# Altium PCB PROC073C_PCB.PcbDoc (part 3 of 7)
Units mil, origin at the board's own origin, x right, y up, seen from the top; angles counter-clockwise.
Board outline 2165.35 x 2695.12 mil, 8 copper layers (Top Layer, L2_GND, L3_SIGNAL 1, L4_SIGNAL 2, L5_SIGNAL 3, L6_SIGNAL 4, L7_GND, Bottom Layer), stack 55.9 mil thick; 393 components, 319 nets, 1311 pads, 1643 vias.
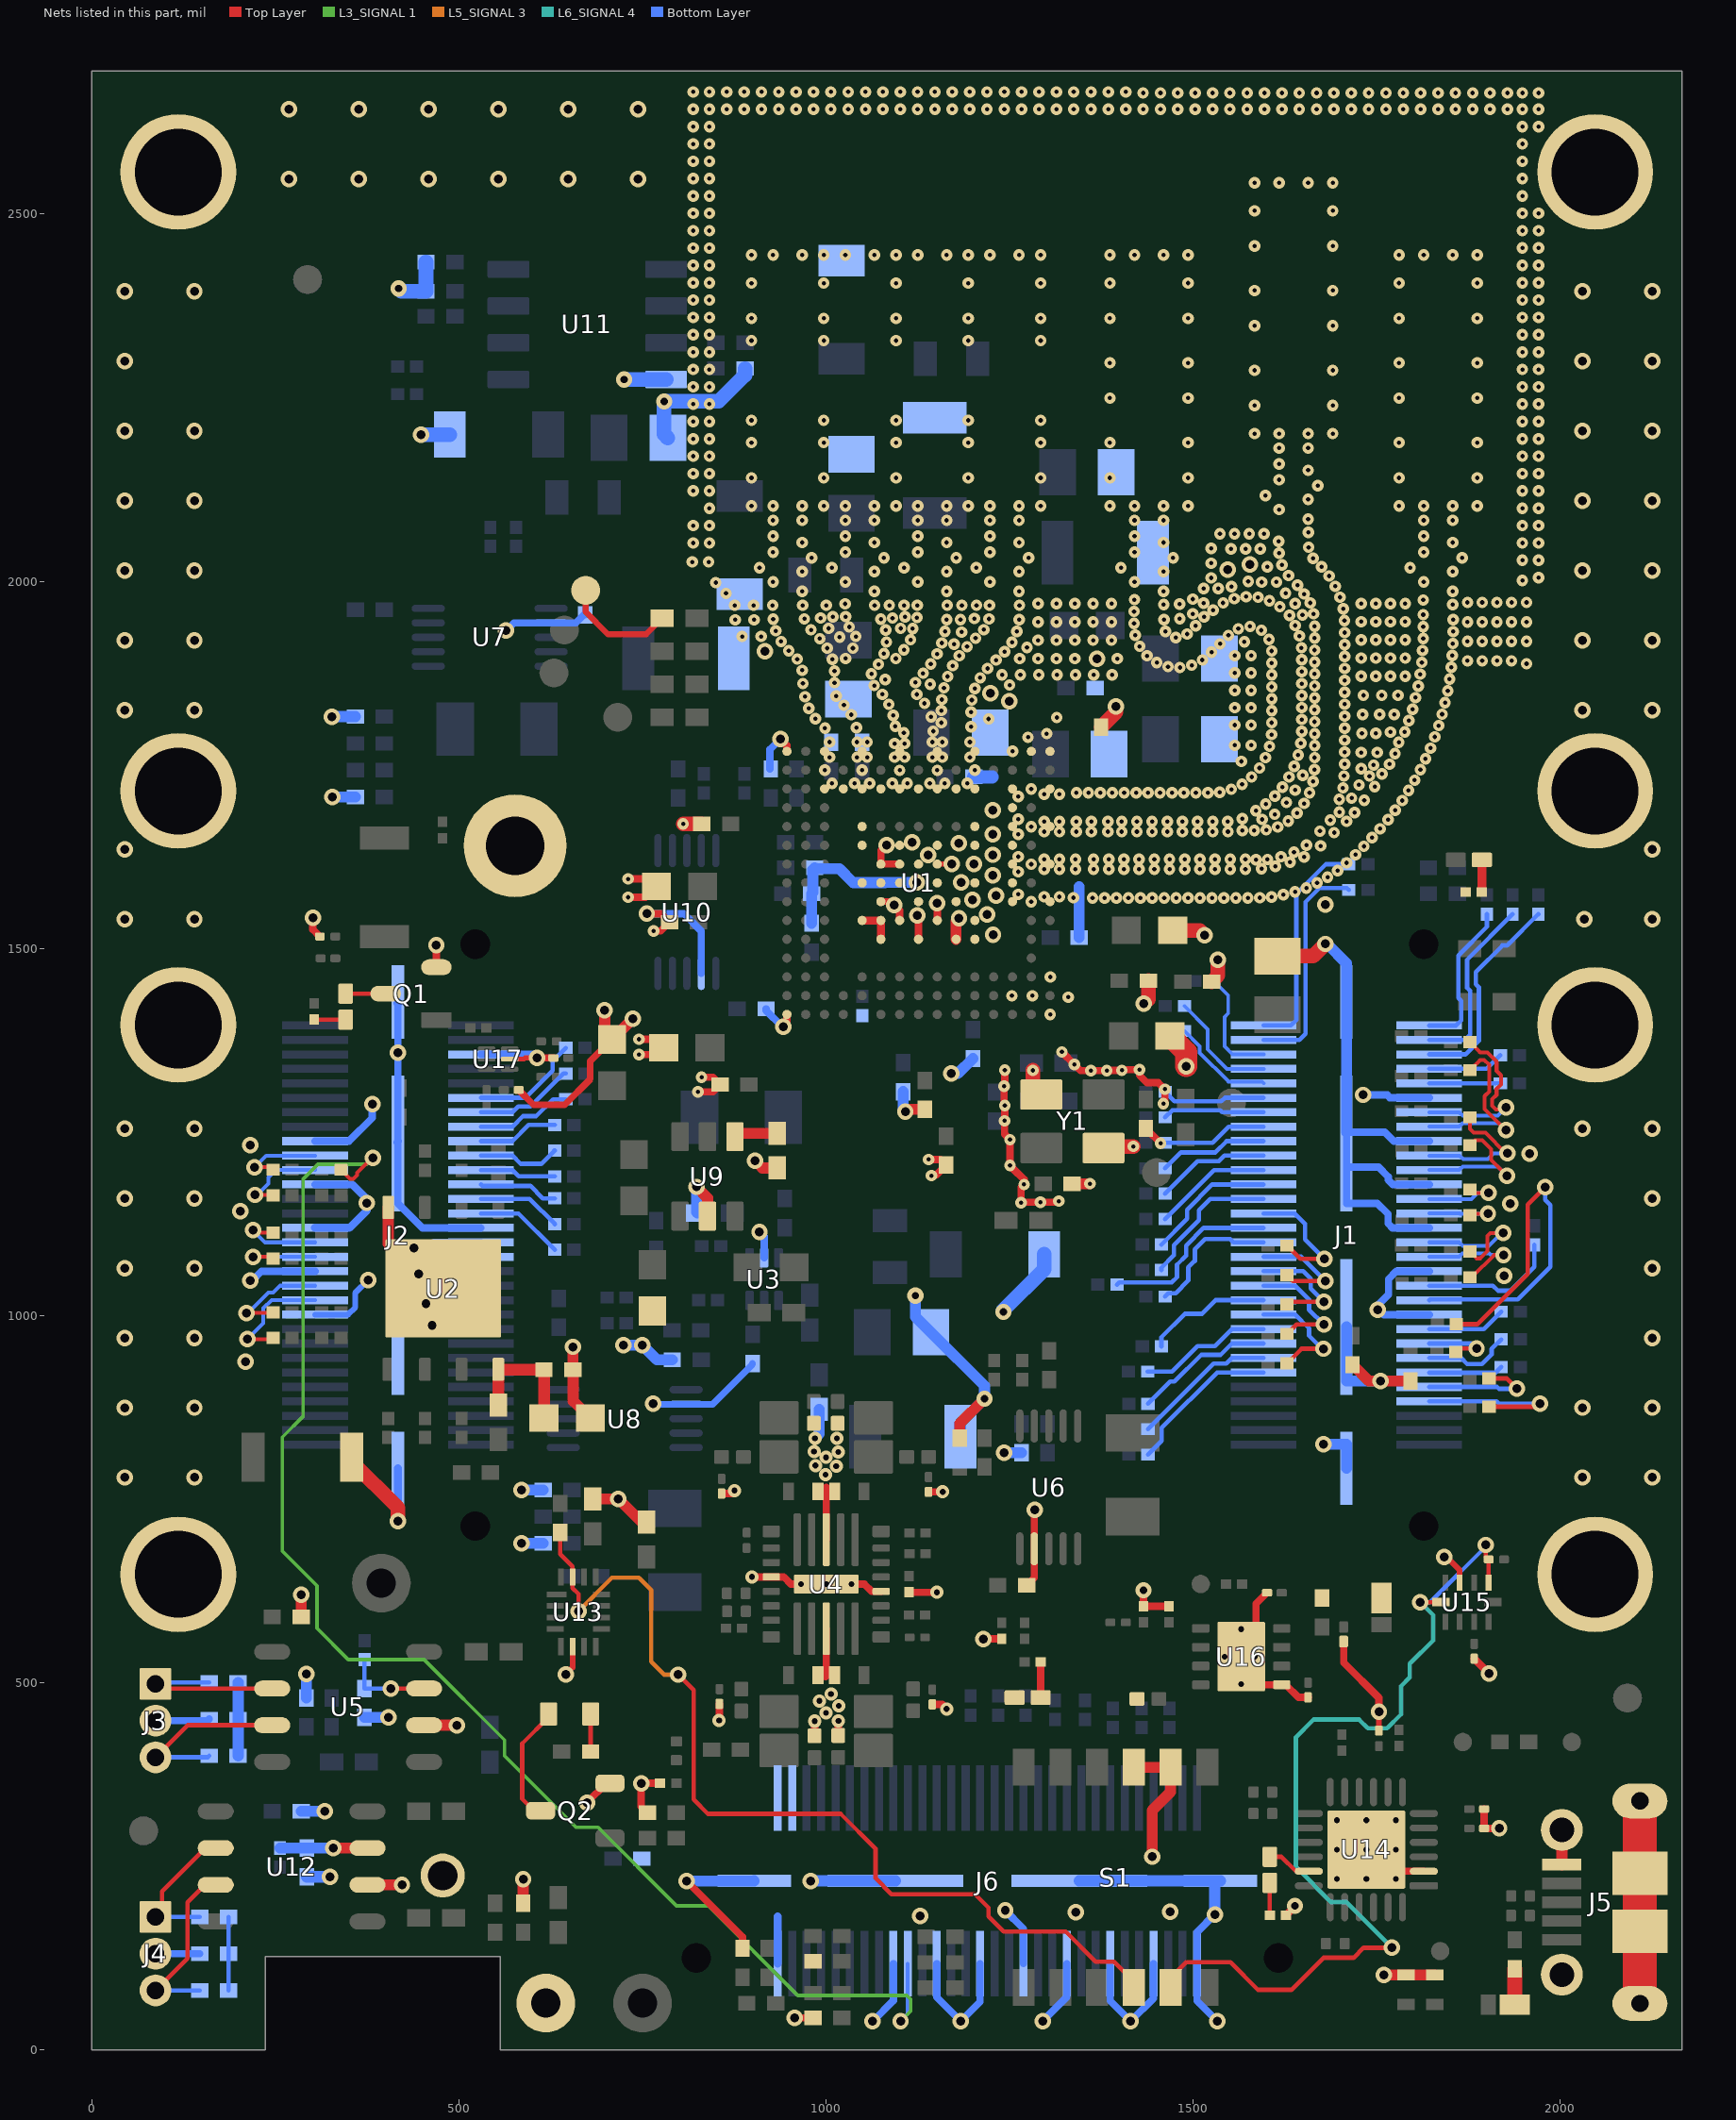
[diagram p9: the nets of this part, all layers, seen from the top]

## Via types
v1: diameter 13.77/15.74 (per signal layer), hole 5.9, Top Layer to L2_GND, tented both sides, 894 vias
v2: diameter 22.4, hole 12.2, Top Layer to Bottom Layer, tented both sides, 510 vias
v3: diameter 18, hole 8, Top Layer to Bottom Layer, tented both sides, 74 vias
v4: diameter 13.78/15.75 (per signal layer), hole 5.9, Top Layer to L2_GND, tented both sides, 72 vias
v5: diameter 22, hole 10, Top Layer to Bottom Layer, tented both sides, 61 vias
v6: diameter 19.68, hole 7.87, Top Layer to Bottom Layer, 16 vias
v7: diameter 13.77/15.74 (per signal layer), hole 5.9, Top Layer to L2_GND, tented top, 14 vias
v8: diameter 20, hole 10, Top Layer to Bottom Layer, tented both sides, 1 vias
v9: diameter 13.78/15.75 (per signal layer), hole 5.9, Top Layer to L2_GND, tented top, 1 vias

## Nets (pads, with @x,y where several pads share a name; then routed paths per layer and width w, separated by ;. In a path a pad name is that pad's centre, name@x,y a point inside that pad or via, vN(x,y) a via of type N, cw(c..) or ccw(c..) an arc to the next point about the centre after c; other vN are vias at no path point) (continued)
GND: C1.1 C2.1 C3.1 C4.1 C5.1 C6.1 C7.1 C8.1 C9.1 C10.1 C11.1 C12.1 C13.1 C14.1 C15.1 C16.1 C17.1 C18.1 C19.1 C20.1 C21.1 C22.1 C23.1 C24.1 C25.1 C26.1 C27.1 C28.1 C29.1 C30.2 C31.1 C32.1 C33.1 C34.1 C35.1 C36.1 C37.1 C38.1 C39.1 C40.1 C41.1 C42.1 C43.2 C44.1 C45.1 C46.1 C47.2 C48.2 C49.2 C50.2 C51.2 C52.1 C53.2 C54.2 C55.2 C56.2 C57.1 C58.1 C59.1 C60.2 C61.2 C62.2 C63.1 C64.1 C65.1 C66.2 C67.2 C68.2 C69.2 C70.2 C71.2 C72.2 C73.2 C74.2 C75.2 C76.2 C77.2 C78.2 C79.2 C80.2 C81.2 C82.2 C83.2 D6.2 J1.20 J1.26 J1.32 J1.38 J1.44 J1.50 J1.MP1 J1.MP2 J1.MP3 J1.MP4 J2.19 J2.25 J2.28 J2.30 J2.31 J2.32 J2.37 J2.43 J2.56 J2.MP1 J2.MP2 J2.MP3 J2.MP4 J3.2 J4.2 J5.5 J5.6 J5.7 J5.8 J5.9 J5.10 J5.11 J6.18 J6.24 J6.30 J6.36 J6.42 J6.48 J6.54 J6.60 J6.MP1 J6.MP2 J6.MP3 J6.MP4 pad.TH1 pad.TH2 pad.TH3 pad.TH4 pad.TH5 pad.TH6 pad.TH7 pad.TH8 pad.TH9 Q1.2 Q2.2 R57.2 R71.2 R84.2 R89.1 R95.1 R99.1 R101.1 R103.1 R113.1 R114.1 R116.1 R117.1 R119.2 R120.1 R121.1 R146.1 R147.1 R152.1 R155.1 R158.1 R162.1 R182.1 R194.1 R197.1 R201.1 R205.1 R208.1 R211.1 R212.2 R215.1 S1.8 S1.9 S2.2 TP11.1 TP12.1 U1.A1 U1.A3 U1.A5 U1.A7 U1.A9 U1.A13 U1.A15 U1.B1 U1.B3 U1.B5 U1.B7 U1.B9 U1.B14 U1.C1 U1.C3 U1.C4 U1.C5 U1.C6 U1.C7 U1.C8 U1.C9 U1.C14 U1.E1 U1.E2 U1.E3 U1.E5 U1.E6 U1.E8 U1.E10 U1.E11 U1.F3 U1.F9 U1.F11 U1.G1 U1.G2 U1.G3 U1.G6 U1.G7 U1.G8 U1.G10 U1.H3 U1.H7 U1.H9 U1.H11 U1.J1 U1.J2 U1.J3 U1.J6 U1.J7 U1.J8 U1.J10 U1.K3 U1.K7 U1.K8 U1.K9 U1.K10 U1.K11 U1.L1 U1.L2 U1.L3 U1.L5 U1.L6 U1.L8 U1.L10 U1.M3 U1.N1 U1.N2 U1.N3 U1.R1 U1.R15 U2.4 U2.9 U3.2 U4.4 U4.11 U4.17 U4.24 U4.27 U5.2 U6.7 U7.7 U8.7 U9.2 U10.7 U11.4 U12.2 U13.6 U14.2 U14.25 U15.3 U16.5 U16.9@1565.44,535.87 U17.2 Y1.2 Y1.4 | length 10819.2
  Top Layer w6.6: U17.2@569.32,1349.48 588.76,1349.48 590.34,1351.06 v2(606.52,1351.06)
  Top Layer w7: U1.J7@1100.38,1613.73 U1.J7@1100.39,1614.98 U1.J7@1100.38,1615.45 ; U1.G7@1151.57,1614.98 U1.G7@1151.57,1614.98 v2(1171.17,1614.99)
  Top Layer w7.87: v2(645.83,511.84) 654.91,520.93 U13.6@654.91,549.7 ; R95.1@1752.9,434.99 v2(1752.9,460.83) ; v2(1842.08,671.49) 1842.08,673.64 1842.33,673.89 1862.92,653.3 U15.3@1862.92,636.55
  Top Layer w9: C53.2@581.57,1307.45 601.6,1287.42 644.39,1287.42 679.2,1322.23 679.2,1346.72 C70.2@708.74,1376.27 ; U1.K9@1074.8,1563.8 1088.56,1563.8 v2(1093.07,1559.29)
  Top Layer w9.42: U14.25@1765.34,243.51 U14.2@1814.14,243.51
  Top Layer w9.8: C57.1@1273.23,632.76 1283.67,643.2 U6.7@1283.67,682.61 1283.67,735.46 v2@1284.13,735.91 ; U16.9@1565.44,535.87 1585.43,555.87 1585.43,607.67 C50.2@1600.53,622.77
  Top Layer w9.84: v2(301.25,1542) 301.25,1526 R215.1@310.87,1516.38 ; v2(606.52,1351.06) C52.1@629.01,1351.06
  Top Layer w10: Q1.2@469.47,1474.62 v2(469.47,1504.44) ; v2(674.94,336.95) 674.94,337.43 Q2.2@700.91,363.4 ; v1(730.59,1569.77) 754.09,1569.77 C17.1@769.1,1584.77 769.09,1585.32 759.39,1595.02 759.14,1594.77 v1(730.59,1594.77) ; v1(745.29,1355.67) 769.99,1355.67 C27.1@779.1,1364.77 767.39,1376.47 v1(745.29,1376.47) ; v2(756,1547.48) 775.19,1547.48 C21.1@786.91,1535.77 775,1523.86 v1(765.4,1523.86) ; R182.1@756.92,323.18 748.32,331.78 v2(748.32,363.4) R201.1@774.18,363.4 ; v2(810.16,230.33) 886.26,154.23 R208.1@886.26,138.67 ; v1(825.59,1304.77) 845.9,1304.77 C25.1@855.91,1314.77 845.9,1324.77 v1(830.59,1324.77) ; v3@854.8,449.13 C54.2@854.8,471.53 C54.2@854.8,471.76 ; C56.2@857.9,757.89 871.42,757.89 v3(875.53,762) ; v3(899.33,644.48) 899.49,644.32 U4.4@925.53,644.32 942.38,644.32 952.22,634.48 v6(966.08,634.48) v6(1000.33,634.48) ; v2(937.97,1785.39) 946.84,1776.52 U1.R1@946.84,1768.52 ; v2(941.65,1393.42) 946.84,1398.61 U1.R15@946.84,1410.25 ; v2(957.39,43.89) R205.1@982.36,43.89 ; C61.2@984.22,427.67 C61.2@984.51,427.96 984.51,447.67 v3(984.8,447.97) ; 999.44,508.58 1000.33,509.47 U4.11@1000.33,573.85 ; 1000.26,766.4 1000.33,766.33 U4.24@1000.33,695.11 ; v6(1000.33,634.48) 1052.53,634.44 1062.34,624.64 U4.17@1075.13,624.64 ; C62.2@1016.44,428.15 C62.2@1016.73,428.44 1016.73,448.15 v3(1017.02,448.44) ; v2(1082.37,1640.84) 1074.79,1633.26 U1.K7@1074.8,1614.98 U1.J7@1100.39,1614.98 ; v2(1093.07,1559.29) 1100.38,1551.98 U1.J10@1100.39,1538.2 ; C68.2@1112.94,623.46 v3(1150.97,623.46) ; v2(1124.47,1544.89) 1125.97,1543.39 U1.H11@1125.98,1512.61 ; C60.2@1139.71,760.24 v3(1158.91,760.24) ; v1(1139.92,1212.73) 1155.94,1212.73 C16.1@1163.59,1205.09 1150.59,1192.08 1145.09,1192.08 v1(1143.74,1190.73) ; C55.2@1144.8,470.87 1158.49,470.87 1164.3,465.06 v3(1164.3,464.54) ; U1.G10@1151.57,1538.2 v2(1151.57,1561.79) ; v2(1214.24,559.92) R194.1@1239.41,559.92 ; v1(1243.49,1334.27) 1243.59,1334.17 1243.59,1313.42 v1(1242.66,1312.49) 1242.66,1286.9 v1(1243.49,1286.07) 1243.49,1265.87 v1(1243.09,1265.47) 1243.09,1247.27 v1(1250.59,1239.77) v1(1250.59,1204.77) 1269.74,1185.62 v1(1269.74,1178.77) 1265.69,1174.72 v1(1265.69,1153.99) ; v1@1250.2,1204.38 1260.59,1193.99 ; v1@1266.29,1154.59 v1(1291.99,1154.59) v1@1315.69,1154.59 ; v1(1321.28,1359.2) v1(1338.23,1342.25) 1346.73,1333.75 v1(1360.63,1333.75) v1(1382.33,1333.75) 1382.73,1334.15 v1(1402.93,1334.15) 1403.93,1335.15 v1(1427.03,1335.15) 1427.03,1327.48 1437.24,1317.26 1452.71,1317.26 v1(1461.53,1308.45) 1461.53,1290.77 v1(1459.43,1288.67) ; Y1.2@1377.91,1228.35 Y1.2@1380.15,1230.59 ; v5(1432.29,626.22) 1432.29,604.6 R120.1@1432.23,604.53 R119.2@1467.08,604.53 ; C32.1@1435.59,1255.09 1435.59,1254.77 v1(1455.59,1234.77) ; U16.9@1565.44,535.87 1565.44,525.48 1593.43,497.49 U16.5@1620.56,497.49 1626.21,497.49 1643.3,480.39 C49.2@1656.37,480.39 ; R99.1@1626.3,183.64 1638.37,195.71 v5(1638.37,196.39) ; C51.2@1704.92,556.41 1704.92,527.79 1752.9,479.81 v2(1752.9,460.83) ; C45.1@1896.13,328.23 C44.1@1896.13,301.92 v2(1916.7,301.92)
  Top Layer w10.34: C48.2@1882.6,533.1 v2(1902.71,512.98)
  Top Layer w11: U1.L10@1049.21,1538.2 U1.K10@1074.8,1538.2 U1.K11@1074.8,1512.61
  Top Layer w15: C38.1@285.31,589.74 v2(285.31,620.19) ; U12.2@375.78,225.13 v2(422.64,225.13) ; U2.4@403.88,1147.43 403.88,1098.19 U2.9@464.88,1037.19 ; U5.2@452.64,442.41 v2(497.63,442.41) ; R84.2@587.71,199.85 v2(587.71,232.68) ; v2(655.38,957.66) C34.1@655.38,926.67 655.76,926.29 655.76,883.87 C35.1@679,860.63 ; C43.2@682.22,750.38 v2(717.37,750.38) 748.9,718.85 R89.1@755.42,718.85 ; v2(698.74,1415.77) 698.74,1386.27 C70.2@708.74,1376.27 v2(736.99,1404.52) ; v2(823.74,1175.44) 838.74,1160.44 U9.2@838.74,1135.64 ; v2(903.51,1211.03) 913.39,1201.15 C71.2@933.74,1201.15 ; v2(1108,1277.77) 1111.31,1281.08 C26.1@1135.59,1281.08 ; U1.F11@1177.16,1512.61 1177.15,1537.17 v2(1181.17,1541.19) ; R101.1@1182.13,833.56 1182.13,853.17 v5(1215.98,887.02) ; C33.1@1335.28,1179.77 v7(1359.59,1179.77) ; S1.9@1419.21,385.15 S1.8@1469.21,385.15 1469.21,351.48 1444.06,326.33 v2(1444.06,263.31) ; R155.1@1717,933.25 1739.05,911.21 v2(1754.94,911.21) R152.1@1795.94,911.21 ; v2(1759.55,102.28) C46.1@1789.78,102.28 C47.2@1828.84,102.28
  Top Layer w15.75: J5.5@2001.97,252.56 J5.10@2001.97,299.81
  Top Layer w20: S2.2@354.03,807.23 354.03,801.78 417.24,738.58 v2(417.24,720.07) ; v1(805.59,1669.77) C28.1@830.91,1669.77 ; v1(1281.8,1334.05) 1281.8,1312.65 Y1.4@1293.27,1301.19 ; C4.1@1374.59,1801.45 1395,1821.86 v2(1395,1829.77) ; Y1.2@1380.15,1230.59 v1(1418.59,1230.59) ; v2(1432.59,1424.77) 1438.87,1431.04 C5.1@1438.87,1456.18 ; C22.1@1472.09,1524.77 1508.78,1524.77 v2(1515.66,1517.89) ; C14.1@1525.28,1454.77 1533.74,1463.23 v2(1533.74,1484.77) ; C15.1@1615,1489.77 1663.54,1489.77 v2(1680,1506.23)
  Top Layer w30: C18.1@1468.28,1381.18 1490.59,1358.86 v2(1490.59,1339.77)
  Top Layer w46: J5.6@2108.27,63.58 J5.7@2108.27,162.01 J5.8@2108.27,240.75 J5.9@2108.27,339.18
  Bottom Layer w8: J2.19@304.44,1001.5 349.08,1001.5 359.13,1011.55 359.13,1030.82 358.98,1030.98 v2(376.73,1048.73)
  Bottom Layer w9: v2@763.74,874.45 768.87,879.59 U8.7@809.52,879.59 846,879.59 900,933.58 C36.1@900,935.09
  Bottom Layer w9.84: J2.56@530.04,1355.83 601.75,1355.83 v2(606.52,1351.06) ; v2(564.49,1932.97) 574.94,1943.43 U7.7@625.74,1943.43 659.49,1943.43 670.12,1954.06 C58.1@672.08,1954.06
  Bottom Layer w10: J4.2@87.13,131.4 C42.1@147.3,131.4 ; J3.2@87.13,448.74 158.26,448.74 C39.1@160.26,450.74 ; v2(216.24,1048.08) 218.91,1048.08 231.39,1060.56 J2.25@304.44,1060.56 ; J2.37@304.44,1178.67 355.06,1178.67 375,1158.73 v2(375,1153.56) ; J2.43@304.44,1237.72 350.49,1237.72 382.3,1269.53 v2(382.3,1288.09) ; J2.MP4@417.24,1427.29 415.92,1425.97 417.41,1424.48 417.02,1424.09 v2(417.02,1358.35) 417.02,1237.97 417.41,1237.58 415.92,1236.09 J2.MP3@417.24,1234.77 417.24,1152.87 450.49,1119.61 J2.32@530.04,1119.61 ; v2(438.88,1092.19) 458.18,1092.19 465.92,1099.93 J2.30@530.04,1099.93 ; v2(445.36,1056.61) 468.99,1080.24 J2.28@530.04,1080.24 ; v2(756,1547.48) 806.28,1547.48 830.27,1523.49 U10.7@830.28,1466.11 ; v2(909.46,1114.3) 915.74,1108.02 U3.2@915.74,1078.9 ; C63.1@918.43,1417.96 918.42,1415.49 940.5,1393.42 v2(941.65,1393.42) ; R146.1@923.74,1744.45 923.74,1771.16 v2(937.97,1785.39) ; v2(1063.3,39.43) 1063.85,39.43 1091.79,67.37 J6.18@1091.79,117.69 ; J6.24@1150.84,117.69 1150.84,72.17 v2(1183.58,39.43) 1209.9,65.74 J6.30@1209.9,117.69 ; v2(1244.15,190.65) v2@1243.52,190.65 ; J6.36@1268.95,117.69 1268.95,165.22 v2@1243.52,190.65 ; v2(1294.98,39.43) 1328.01,72.46 J6.42@1328.01,117.69 ; J6.48@1387.06,117.69 1387.06,67.26 v2(1414.9,39.43) 1445.89,70.42 1445.89,117.46 J6.54@1446.12,117.69 ; v2(1529.43,184.88) 1505.17,160.61 J6.60@1505.17,117.69 1505.17,67.26 v2(1533.01,39.43) ; v2(1731.57,1300.7) 1731.76,1300.52 1764.48,1300.52 1767.77,1297.23 ; 1767.77,1296.78 J1.50@1821.54,1296.78 ; 1775.49,1119.61 J1.32@1821.54,1119.61 1771.25,1119.61 1765.35,1125.52 1765.35,1138.41 1750.74,1153.01 1708.74,1153.01 J1.MP3@1708.74,1202.38 ; J1.20@1821.54,1001.5 1759.57,1001.5 1753.07,1008 v2(1751.37,1008) 1751.37,1014.28 1765.97,1028.88 1765.97,1049.94 1776.59,1060.56 J1.26@1821.54,1060.56 ; J1.38@1821.54,1178.67 1771.93,1178.67 1765.62,1184.98 1765.62,1189.3 1752.54,1202.38 J1.MP3@1708.74,1202.38 ; J1.44@1821.54,1237.72 1773.14,1237.72 1760.84,1250.02 1708.74,1250.02 J1.MP3@1708.74,1234.77 J1.MP3@1708.74,1202.38 ; v2@1243.52,190.65 1243.16,191.01 1243.03,190.88 1243.25,190.65 v2@1243.52,190.65
  Bottom Layer w11: J2.31@304.44,1119.61 351.2,1119.61 375,1143.42 v2(375,1153.56) ; v2(417.24,720.07) J2.MP1@417.24,792.25
  Bottom Layer w15: C41.1@285.33,325.13 v2(317.37,325.13) ; R71.2@292.59,479.59 v2(292.59,512.16) ; v2(326.97,1815.73) R113.1@359.16,1815.75 ; v2(327.89,1706.46) R114.1@359.16,1706.46 ; C37.1@371.69,453.04 v2(404.26,453.04) ; J2.MP2@417.24,984.77 419.2,986.73 v2(463.71,986.73) ; v2(585.46,690.14) R117.1@614.95,690.14 ; v2(585.46,762.57) R116.1@614.95,762.57 ; v2(723.95,959.77) v2(750,959.77) 769.68,940.08 C59.1@790.63,940.08 ; v2(810.16,230.33) 902.07,230.33 J6.MP1@902.22,230.48 ; v2(823.74,1175.44) 823.74,1141.15 R197.1@825.12,1139.77 ; v2(979.45,230.48) J6.MP2@1094.74,230.48 ; C10.1@980.28,1574.77 980.27,1534.77 C29.1@980.59,1534.45 ; C10.1@980.28,1574.77 982.13,1576.62 982.13,1607.21 R147.1@984.69,1609.77 985.87,1608.59 1018.39,1608.59 1037.21,1589.77 1079.88,1589.77 1080,1589.89 v2(1123.47,1589.89) ; v3(985.07,833.21) 990.93,839.07 R57.2@990.93,872.48 ; C30.2@1105,1305.08 1105,1280.77 v2(1108,1277.77) ; v5(1121.81,1027.3) 1121.81,998.47 C83.2@1142.52,977.76 ; C83.2@1142.93,977.35 1215.98,904.3 v5(1215.98,887.02) 1183.23,854.27 C82.2@1183.23,835.48 ; v2(1170.59,1329.77) 1179.68,1329.77 C9.1@1200,1350.09 ; v2(1242.56,813.46) R103.1@1266.47,813.46 ; C6.1@1344.69,1514.77 1344.68,1584.45 ; J6.MP3@1344.74,230.48 J6.MP4@1531.53,230.48 ; v2(1529.43,184.88) 1529.43,228.38 J6.MP4@1531.53,230.48 ; J6.MP4@1537.26,230.48 J6.MP4@1531.53,230.48 ; v2(1677.33,824.84) 1708.74,824.84 J1.MP1@1708.74,792.25 ; v2(1680,1506.23) 1682.3,1506.23 1708.74,1479.79 J1.MP4@1708.74,1427.29 J1.MP3@1708.74,1250.02 ; J1.MP2@1708.74,984.77 1708.74,911.21 v2(1754.94,911.21)
  Bottom Layer w16: C40.1@293.22,235.76 v2(324.43,235.76)
  Bottom Layer w18: C12.1@1201.28,1733.77 1226,1733.77
  Bottom Layer w20: v5(418,2398.77) 422,2394.77 R158.1@455.32,2394.77 C65.1@455.32,2434.77 ; v2(448.61,2199.7) C64.1@487.92,2199.7 ; v5(725,2274.77) U11.4@782.28,2274.77 ; C81.2@784.63,2195.15 779.59,2200.19 v5(779.59,2245.04) 853.81,2245.04 889.68,2280.92 R162.1@889.69,2289.77 ; v5(1241.47,1005.29) 1241.47,1007.6 1297.08,1063.21 C1.1@1297.08,1083.72
  other v1: 1317.09,1155.99 1305.31,1410.05 1330,1433.77 1253.08,1435.63 1281.08,1435.63 1305.58,1461.22 1279.52,1563.79 1337.05,1569.18 1362.97,1568.78 1379.24,1568.78 1395.5,1568.78 1411.77,1568.78 1428.03,1568.78 1444.3,1568.78 1460.56,1568.78 1476.83,1568.78 1493.09,1568.78 1509.36,1568.78 1525.62,1568.78 1541.89,1568.78 1558.15,1568.78 1574.42,1568.78 1590.68,1569.15 1606.91,1570.21 1297.24,1570.4 1317.9,1570.4 1622.9,1573.19 1261.81,1573.82 1638.67,1577.17 1654.07,1582.39 1668.78,1589.34 1683.02,1597.19 1261.81,1604.53 1696.54,1606.23 1297.24,1607.95 1317.9,1607.95 1279.52,1614.77 1709,1616.68 1297.23,1621.58 1317.89,1621.58 1261.8,1625 1720.95,1627.71 1732.45,1639.22 1673.43,1639.68 1743.69,1650.98 1261.8,1655.71 1297.23,1659.13 1317.89,1659.13 1566.95,1660.76 1583.22,1660.76 1599.46,1661.55 1754.61,1663.03 1279.51,1665.95 1615.23,1665.56 1297.23,1672.76 1317.89,1672.76 1547,1672.77 1708.91,1673.15 1629.44,1673.45 1261.8,1676.18 1765.24,1675.34 1567,1676.77 1641.4,1684.48 1719.83,1685.2 1585.34,1687.75 1774.93,1688.4 1598.86,1696.79 1651.14,1697.51 1784.62,1701.47 1698.87,1703.23 1715.74,1704.77 1261.8,1706.89 1611.09,1707.52 1297.23,1710.31 1317.89,1710.31 1341,1711.94 1357.27,1711.94 1373.53,1711.94 1389.8,1711.94 1406.06,1711.94 1422.33,1711.94 1438.59,1711.94 1454.86,1711.94 1471.12,1711.94 1487.39,1711.94 1503.65,1711.94 1519.92,1711.94 1658.5,1712.01 1536.15,1712.84 1793.23,1715.27 1279.51,1717.13 1551.94,1716.75 1621.65,1719.88 1725.74,1722.77 1566.61,1723.78 1008.26,1725.01 1038.97,1725.01 1059.44,1725.01 1090.15,1725.01 1110.62,1725.01 1141.33,1725.01 1161.8,1725.01 1192.51,1725.01 1663.26,1727.56 1801.59,1729.22 1579.54,1733.64 1630.47,1733.55 1705.38,1735.05 1740,1734.77 1049.21,1742.93 1100.39,1742.72 1151.57,1742.72 1202.75,1742.93 1665.28,1743.7 1809.41,1743.48 1728.74,1744.93 1590.31,1745.83 1637.61,1748.16 1745.74,1749.77 1767.26,1751.02 1706.22,1751.29 1565.74,1754.77 1816.36,1758.18 1598.46,1759.9 1665.42,1759.97 1004.84,1760.44 1042.39,1760.44 1056.02,1760.44 1093.57,1760.44 1107.2,1760.44 1144.75,1760.44 1158.38,1760.44 1195.93,1760.44 1642.96,1763.53 1774.81,1765.42 1728.74,1766.93 1750.74,1766.93 1706.22,1767.56 1254.13,1768.73 1823.27,1772.91 1603.95,1775.22 1665.42,1776.23 1556.74,1776.72 1578.9,1776.72 1093.57,1779.1 1107.2,1779.1 1646.44,1779.41 1004.84,1781.1 1042.39,1781.1 1056.02,1781.1 1144.75,1781.1 1158.38,1781.1 1195.93,1781.1 1706.22,1783.82 1275.08,1787.63 1828.85,1788.19 1606.59,1791.26 1300.58,1792.63 1665.42,1792.49 1729.74,1792.88 1748.74,1792.88 1106,1793.77 1768.74,1794.77 1788.14,1795.09 1146.02,1795.85 1647.72,1795.63 998.62,1799.93 1706.22,1800.09 1041.46,1800.71 1197.56,1801.87 1094.35,1802.77 1834.33,1803.5 1556.74,1804.28 1578.9,1804.28 1157.08,1807.49 1607,1807.52 1665.42,1808.76 1793.62,1810.41 1647.79,1811.89 985.62,1812.93 1221.58,1812.63 1314.28,1814.53 1143.22,1815.56 1706.22,1816.35 1091.55,1817.33 1034.33,1818.45 1730.74,1818.82 1753.74,1818.82 1773.74,1818.82 1838.99,1819.08 1197.56,1822.07 1157.08,1824.03 1607,1823.79 1665.42,1825.02 1798.77,1825.83 976.62,1826.93 1556.74,1827.9 1578.9,1827.9 1647.79,1828.16 1024.45,1831.37 1085.58,1832.46 1706.22,1832.62 1134.21,1833.76 1842.94,1834.86 1157.74,1838.9 1198.59,1838.3 1607,1840.05 1665.42,1841.29 1802.72,1841.61 971.62,1842.93 1013.89,1843.74 1647.79,1844.42 1731.74,1844.77 1756.74,1844.77 1778.74,1844.77 1076.69,1846.08 1123.56,1846.05 1706.22,1848.88 1846.71,1850.68 1556.74,1851.52 1578.9,1851.52 1202.74,1854.03 1160.66,1854.9 1607,1856.32 1065.72,1858.09 1665.42,1857.55 1806.61,1857.4 1250,1858.77 1141.94,1859.75 968.62,1860.93 1647.79,1860.69 1011.62,1861.93 1121.92,1862.23 1706.22,1865.14 1080.65,1866.12 1849.1,1866.77 1209.99,1868.59 1165.67,1870.38 1728.74,1870.71 1748.74,1870.71 1768.74,1870.71 1788.74,1870.71 1239.74,1872.77 1264.74,1872.77 1289.74,1872.77 1314.74,1872.77 1339.74,1872.77 1364.74,1872.77 1389.74,1872.77 1607,1872.58 1061.86,1873.89 1665.42,1873.82 1809,1873.49 1132.26,1874.79 1556.74,1875.15 1578.9,1875.15 1647.79,1876.95 1011.62,1877.93 967.62,1878.93 1220.05,1881.37 1706.22,1881.41 1481.97,1882.64 1851.49,1882.86 1465.75,1883.83 1172.66,1885.06 1497.93,1885.74 1071.51,1886.98 1142.67,1887.29 1953.98,1887.82 1607,1888.85 1450.42,1889.28 1665.42,1890.08 1811.38,1889.58 1873.55,1891.76 1893.53,1891.76 1913.54,1891.76 1933.52,1891.76 1231.62,1892.8 1512.54,1892.9 1647.79,1893.21 960.84,1894.05 1008.62,1893.93 1026.62,1894.93 1095.15,1894.89 1263.74,1894.77 1288.74,1894.77 1313.74,1894.77 1338.74,1894.77 1396.74,1894.77 1728.74,1895.48 1748.74,1895.48 1768.74,1895.48 1788.74,1895.48 1706.22,1897.67 1181.53,1898.69 1437.1,1898.61 1556.74,1898.77 1578.9,1898.77 1852.78,1899.07 1151.18,1901.15 1078.92,1901.46 1243.21,1904.21 1524.97,1903.39 1607,1905.11 949.34,1905.55 1812.41,1905.81 1106.16,1906.86 1665.42,1906.35 1001.62,1908.93 1036.62,1908.93 1273.74,1909.77 1647.44,1909.48 1192.14,1911.02 1427.08,1911.42 1706.22,1913.94 1174.3,1914.4 1536.47,1914.89 1157.62,1916.08 1853.58,1915.32 1253.2,1917.04 938.95,1918.07 1082.34,1917.36 1569.74,1917.77 1873.55,1918.26 1893.53,1918.26 1913.54,1918.26 1933.52,1918.26 1953.98,1918.26 1288.74,1919.77 1313.74,1919.77 1338.74,1919.77 1363.74,1919.77 1388.74,1919.77 1728.74,1920.24 1748.74,1920.24 1768.74,1920.24 1788.74,1920.24 1115.1,1920.45 1603.27,1920.94 991.62,1921.93 1813.21,1922.06 1203.64,1922.52 1665.42,1922.61 1018.62,1923.93 1476.3,1923.45 885.86,1924.93 911.74,1924.93 1040.62,1924.93 1644.78,1925.52 1420.97,1926.49 1547.97,1926.39 1491.83,1928.26 1706.22,1930.2 1184.62,1930.93 1162.03,1931.74 1259.92,1931.86 1462.28,1931.69 1854.01,1931.57 931.71,1932.63 979.62,1933.93 1081.18,1933.58 1215.08,1934.08 1592.84,1933.42 1003.62,1935.93 1101.66,1935.93 1561.5,1935.43 1031.62,1937.93 1577.44,1938.65 1665.42,1938.88 1813.21,1938.32 1503.49,1939.6 1419.51,1942.69 1288.74,1944.77 1313.74,1944.77 1338.74,1944.77 1363.74,1944.77 1388.74,1944.77 1728.74,1945 1748.74,1945 1768.74,1945 1788.74,1945 1873.55,1944.77 1893.53,1944.77 1913.54,1944.77 1933.52,1944.77 1953.98,1944.77 1706.05,1946.47 876.33,1947.65 902.2,1947.65 1164.35,1947.84 1263,1947.83 1460.31,1947.84 1854.01,1947.84 928.08,1948.48 970.62,1948.93 1074.71,1948.51 1222.11,1948.75 1481.65,1949.03 992.62,1949.93 1090.66,1949.93 1202.2,1949.34 1009.47,1951.64 1026.62,1951.93 1107.51,1951.64 1515,1951.77 1648.83,1954.15 1813.21,1954.59 1499.62,1955.71 1419.51,1958.96 1527,1960.77 1704.44,1962.65 1617.97,1965.39 875.62,1967.34 901.49,1967.34 927.37,1967.34 968.17,1967.34 1000.3,1967.34 1066.23,1967.34 1086.21,1967.33 1106.22,1967.34 1124.23,1967.34 1165.03,1967.34 1185,1967.33 1205.02,1967.34 1222.65,1967.34 1263.45,1967.34 1459.84,1968.26 1853.54,1968.26 1481.64,1969.04 1288.74,1969.77 1313.74,1969.77 1338.74,1969.77 1363.74,1969.77 1388.74,1969.77 1638.99,1969.78 1728.74,1969.77 1748.74,1969.77 1768.74,1969.77 1788.74,1969.77 1514.23,1970.32 1540.83,1970.69 1659.55,1970.65 1893.53,1971.26 1933.52,1971.26 1953.98,1971.26 1873.55,1971.27 1913.54,1971.27 1603.91,1973.56 1420.03,1975.02 1813.21,1974.59 1499.61,1975.72 1556.03,1976.47 1588.33,1978.22 1572.08,1979.07 1700.01,1978.3 863.94,1983.55 1625.84,1983.79 967.55,1986.23 1065.98,1986.23 1164.41,1986.23 1262.84,1986.23 1459.7,1986.25 1853.4,1986.25 1514.22,1990.33 1534.23,1990.34 1552,1992.77 1693.57,1993.24 849.84,1998.23 1593.39,1998.94 1613.4,1998.95 1575,1999.77 1948.27,2001.08 1524.57,2004.68 1970.43,2005.02 1685.24,2007.2 967.55,2013.26 1065.98,2013.26 1164.41,2013.26 1262.84,2013.26 1459.69,2013.27 1853.39,2013.27 909.5,2018.47 1007.93,2018.47 1106.36,2018.47 1204.79,2018.47 1401.65,2018.48 1795.35,2018.48 1601,2019.77 1674.91,2019.77 1620.8,2022.48 1524.56,2024.69 818.11,2026.42 840.27,2026.42 1948.27,2028.64 1970.43,2028.64 1663.37,2031.23 980.54,2031.85 1078.97,2031.85 1177.4,2031.85 1275.83,2031.85 1472.69,2031.86 1866.39,2031.86 1616.87,2038.26 928,2039.8 1026.43,2039.8 1124.86,2039.8 1223.29,2039.8 1420.15,2039.82 1813.85,2039.82 1551.47,2044.1 1571.48,2044.11 1591.46,2044.1 1524.57,2044.67 1657.16,2046.26 819.09,2052.25 841.26,2052.25 1948.27,2052.26 1970.43,2052.26 967.56,2052.8 1065.99,2052.8 1164.42,2052.8 1262.85,2052.8 1459.69,2052.82 1853.39,2052.82 1616.36,2054.52 927.99,2061.43 1026.42,2061.43 1124.85,2061.43 1223.28,2061.43 1420.14,2061.44 1813.84,2061.44 1536.37,2064.68 1556.35,2064.67 1576.36,2064.68 1596.34,2064.67 1656.69,2066.69 819.09,2075.87 841.26,2075.87 1948.27,2075.89 1970.43,2075.89 928,2083.03 967.55,2083.03 1026.43,2083.03 1065.98,2083.03 1124.86,2083.03 1164.41,2083.03 1223.29,2083.03 1262.84,2083.03 1420.15,2083.05 1459.69,2083.05 1813.85,2083.05 1853.39,2083.05 1656.55,2084.67 841.26,2099.49 1948.27,2099.51 1970.43,2099.51 898.55,2102.72 928,2102.72 967.55,2102.72 997,2102.72 1026.43,2102.72 1065.98,2102.72 1095.43,2102.72 1124.86,2102.72 1164.41,2102.72 1193.86,2102.72 1223.29,2102.72 1262.84,2102.72 1292.29,2102.72 1386.65,2102.73 1420.15,2102.73 1459.69,2102.73 1493.18,2102.73 1780.35,2102.73 1813.85,2102.73 1853.39,2102.73 1886.88,2102.73 1656.54,2111.7 1598.5,2116.9 819.09,2123.11 841.26,2123.11 1948.27,2123.13 1970.43,2123.13 1669.54,2130.29 1617,2138.25 898.55,2140.87 996.98,2140.89 1095.41,2140.89 1193.84,2140.89 1292.27,2140.89 1386.65,2140.88 1493.18,2140.88 1780.35,2140.88 1886.88,2140.88 819.09,2146.74 841.26,2146.74 1948.27,2146.75 1970.43,2146.75 1656.54,2151.24 1616.99,2159.87 819.09,2170.36 841.26,2170.36 1948.27,2170.37 1970.43,2170.37 1617,2181.47 1656.54,2181.47 898.55,2188.9 996.97,2188.9 1095.4,2188.9 1193.83,2188.9 1292.26,2188.9 1386.65,2188.91 1493.18,2188.91 1780.35,2188.91 1886.88,2188.91 819.09,2193.98 841.26,2193.98 1948.27,2194 1970.43,2194 1583.5,2201.16 1617,2201.16 1656.54,2201.16 1690.03,2201.16 819.09,2217.6 841.26,2217.6 1948.27,2217.62 1970.43,2217.62 898.55,2219.17 996.97,2219.17 1095.4,2219.17 1193.83,2219.17 1292.26,2219.17 1583.5,2239.3 1690.03,2239.3 819.09,2241.22 841.26,2241.22 1948.27,2241.24 1970.43,2241.24 1386.65,2249.46 1493.18,2249.46 1780.35,2249.46 1886.88,2249.46 819.09,2264.85 841.26,2264.85 1948.27,2264.86 1970.43,2264.86 1583.5,2287.34 1690.03,2287.34 819.09,2288.47 841.26,2288.47 1948.27,2288.48 1970.43,2288.48 1386.65,2297.49 1493.18,2297.49 1780.35,2297.49 1886.88,2297.49 819.09,2312.09 841.26,2312.09 1948.27,2312.11 1970.43,2312.11 898.55,2327.76 996.97,2327.76 1095.4,2327.76 1193.83,2327.76 1292.26,2327.76 819.09,2335.71 841.26,2335.71 1948.27,2335.73 1970.43,2335.73 1583.5,2347.89 1690.03,2347.89 898.55,2358.03 996.97,2358.03 1095.4,2358.03 1193.83,2358.03 1292.26,2358.03 1386.65,2358.05 1493.18,2358.05 1780.35,2358.05 1886.88,2358.05 819.09,2359.34 841.26,2359.34 1948.27,2359.35 1970.43,2359.35 819.09,2382.96 841.26,2382.96 1948.27,2382.97 1970.43,2382.97 1583.5,2395.92 1690.03,2395.92 898.55,2406.06 996.97,2406.06 1095.4,2406.06 1193.83,2406.06 1292.26,2406.06 1386.65,2406.08 1493.2,2406.08 1780.35,2406.08 1886.9,2406.08 819.09,2406.58 841.26,2406.58 1948.27,2406.59 1970.43,2406.59 819.09,2430.2 841.26,2430.2 1948.27,2430.22 1970.43,2430.22 898.55,2444.21 928,2444.21 967.56,2444.21 996.97,2444.21 1026.43,2444.21 1065.99,2444.21 1095.4,2444.21 1124.86,2444.21 1164.42,2444.21 1193.83,2444.21 1223.29,2444.21 1262.85,2444.21 1292.26,2444.21 1386.65,2444.23 1420.15,2444.23 1459.69,2444.23 1493.2,2444.23 1780.35,2444.23 1813.85,2444.23 1853.39,2444.23 1886.9,2444.23 819.09,2453.82 841.26,2453.82 1948.27,2453.84 1970.43,2453.84 1583.5,2456.47 1690.03,2456.47 819.09,2477.45 841.26,2477.45 1948.27,2477.46 1970.43,2477.46 819.09,2501.07 841.26,2501.07 1948.27,2501.08 1970.43,2501.08 1583.5,2504.5 1690.05,2504.5 819.09,2524.69 841.26,2524.69 1948.27,2524.7 1583.5,2542.65 1617,2542.65 1656.54,2542.65 1690.05,2542.65 819.09,2548.31 841.26,2548.31 1948.27,2548.33 819.09,2571.93 841.26,2571.93 1948.27,2571.95 819.09,2595.56 841.26,2595.56 1948.27,2595.57 819.09,2619.18 841.26,2619.18 1948.27,2619.19 1970.43,2619.19 819.09,2642.8 841.26,2642.8 864.88,2642.8 888.5,2642.8 912.13,2642.8 935.75,2642.8 959.37,2642.8 982.99,2642.8 1006.61,2642.8 1030.24,2642.8 1053.86,2642.8 1077.48,2642.8 1101.1,2642.8 1124.72,2642.8 1148.35,2642.8 1171.97,2642.8 1195.59,2642.8 1219.21,2642.8 1242.83,2642.8 1266.46,2642.8 1290.08,2642.8 1313.7,2642.8 1337.32,2642.8 1360.94,2642.8 1384.57,2642.8 1408.19,2642.8 1431.81,2642.8 1455.43,2642.8 1479.05,2642.8 1502.68,2642.8 1526.3,2642.8 1549.92,2642.8 1573.54,2642.8 1597.16,2642.8 1620.79,2642.8 1644.41,2642.8 1668.03,2642.8 1691.65,2642.8 1715.27,2642.8 1738.9,2642.8 1762.52,2642.8 1786.14,2642.8 1809.76,2642.8 1833.38,2642.8 1857.01,2642.8 1880.63,2642.8 1904.25,2642.8 1927.87,2642.8 1948.27,2642.8 1970.43,2642.8 1431.81,2664.96 1455.43,2664.96 1479.05,2664.96 1502.68,2664.96 1526.3,2664.96 1549.92,2664.96 1573.54,2664.96 1597.16,2664.96 1620.79,2664.96 1644.41,2664.96 1668.03,2664.96 1691.65,2664.96 1715.27,2664.96 1738.9,2664.96 1762.52,2664.96 1786.14,2664.96 1809.76,2664.96 1833.38,2664.96 1857.01,2664.96 1880.63,2664.96 1904.25,2664.96 1927.87,2664.96 1948.27,2664.96 1970.43,2664.96 819.09,2666.42 841.26,2666.42 864.88,2666.42 888.5,2666.42 912.13,2666.42 935.75,2666.42 959.37,2666.42 982.99,2666.42 1006.61,2666.42 1030.24,2666.42 1053.86,2666.42 1077.48,2666.42 1101.1,2666.42 1124.72,2666.42 1148.35,2666.42 1171.97,2666.42 1195.59,2666.42 1219.21,2666.42 1242.83,2666.42 1266.46,2666.42 1290.08,2666.42 1313.7,2666.42 1337.32,2666.42 1360.94,2666.42 1384.57,2666.42 1408.19,2666.42
  other v2: 1128.1,182.74 1339.94,187.99 1468.86,188.66 1284.15,735.91 45,779.77 140,779.77 2030,779.77 2125,779.77 45,874.77 140,874.77 2030,874.77 2125,874.77 764.92,880.41 209.88,937.24 45,969.77 140,969.77 2125,969.77 455.36,1016.61 1923.33,1054.31 45,1064.77 140,1064.77 2125,1064.77 202.55,1142.16 1931.64,1152.64 45,1159.77 140,1159.77 2125,1159.77 1958.02,1220.93 215.88,1232.14 45,1254.77 140,1254.77 2030,1254.77 2125,1254.77 1227.47,1518.64 45,1539.77 140,1539.77 2032.46,1539.86 2125,1539.77 1219.57,1546.44 1680,1559.77 1199.37,1566.04 1231.37,1571.94 1184.17,1589.89 1226.87,1599.59 1201.17,1614.99 1139.07,1627.44 1227.07,1627.59 45,1634.77 2125,1634.77 1180.97,1643.59 1117.07,1644.77 1227.07,1655.59 1226.87,1688.44 45,1824.77 140,1824.77 2030,1824.77 2125,1824.77 1249.69,1836.72 1224,1847.77 1369.04,1894.57 916.93,1904.77 45,1919.77 140,1919.77 2030,1919.77 2125,1919.77 45,2014.77 140,2014.77 2030,2014.77 2125,2014.77 1547,2015.77 1577,2022.77 45,2109.77 140,2109.77 2030,2109.77 2125,2109.77 45,2204.77 140,2204.77 2030,2204.77 2125,2204.77 45,2299.77 2030,2299.77 2125,2299.77 45,2394.77 140,2394.77 2030,2394.77 2125,2394.77 269,2547.77 364,2547.77 459,2547.77 554,2547.77 649,2547.77 744,2547.77 269,2642.77 364,2642.77 459,2642.77 554,2642.77 649,2642.77 744,2642.77
  other v3: 854.47,448.79 999.94,459.06 1017.5,468.74 991.22,475.45 1006.94,485 999.53,783.47 1013.98,795.27 985.65,796.09 1000.09,807.05 983.78,814.94 1016.65,814.42 1014.69,832.88
  other v4: 1339.76,1607.96 1364.4,1607.96 1385.07,1607.96 1405.74,1607.96 1426.41,1607.96 1447.08,1607.96 1467.75,1607.96 1488.42,1607.96 1509.09,1607.96 1529.75,1607.96 1550.42,1607.96 1571.09,1607.96 1593,1608.77 1612,1611.77 1632,1617.77 1585.71,1620.83 1339.76,1621.59 1364.4,1621.59 1385.07,1621.59 1405.74,1621.59 1426.4,1621.59 1447.07,1621.59 1467.74,1621.59 1488.41,1621.59 1509.08,1621.59 1529.75,1621.59 1550.42,1621.59 1571.09,1621.59 1601.22,1621.34 1619.68,1624.97 1651,1624.77 1637.28,1631.26 1654.18,1640.85 1692,1657.77 1340.67,1659.13 1361.34,1659.13 1383.87,1659.13 1402.68,1659.13 1423.35,1659.13 1444.02,1659.13 1464.69,1659.13 1485.36,1659.13 1506.03,1659.13 1526.68,1659.13 1547.33,1659.13 1672.56,1659.81 1340.67,1672.77 1361.34,1672.77 1383.87,1672.77 1402.68,1672.77 1423.35,1672.77 1444.02,1672.77 1464.69,1672.77 1485.36,1672.77 1506.03,1672.77 1526.68,1672.77 1686.76,1674.81 1594,1675.77 1611,1682.77 1627,1698.77 1733,1701.77 1639,1715.77 1704,1718.77 1649,1735.77 1757,1737.77 1780,1780.77 1639,1939.77 1631,1953.77 1664,1955.77 1651,1982.77 1642,1994.77 1630,2007.77
  other v6: 1695.81,233.04 1735.81,233.04 1775.81,233.04 1695.81,273.04 1735.81,273.04 1775.81,273.04 1695.81,313.04 1735.81,313.04 1775.81,313.05 1565.44,498.47 1542.8,535.87 1583.85,535.88 1565.44,573.28 1034.58,634.48
  other v7: 1747.21,1720.32 998.5,1742.93 1118.1,1935.57 1183.1,1947.94 1123.89,1950.59 1026.18,1969.34 928,1999.24 1026.43,1999.24 1124.86,1999.24 1223.29,1999.24 1420.15,1999.25 1813.85,1999.25 1617,2097.67
  other v9: 1699,1685.77
MON_1V: R72.1 TP2.1 | length 155.1
  Top Layer w8: TP2.1@672.85,1987.78 672.85,1958.4 703.21,1928.04 755.24,1928.04 R72.1@776.97,1949.77
MUX_IN_1: R88.1 S1.4 U13.15 | length 1303.2
  Top Layer w6: R88.1@638.24,705.01 638.24,675.18 654.91,658.5 U13.15@654.91,644.19 654.91,629.36 663.21,621.07 v2(663.21,597.83) ; v2(798.79,511.28) 819.73,490.34 819.73,341.35 839.35,321.73 1019.97,321.73 1067.56,274.14 1067.56,233.88 1089.2,212.23 1203.02,212.23 1221.31,193.95 1221.31,182.1 1242.12,161.28 1326.39,161.28 1367.15,120.53 1392.01,120.53 1419.21,93.33 S1.4@1419.21,85.15
  L5_SIGNAL 3 w6: v2(663.21,597.83) 708.45,643.08 745.41,643.08 762.13,626.36 762.13,528.71 779.57,511.28 v2(798.79,511.28)
MUX_IN_2: R100.1 S1.5 U15.1 U15.5 | length 1266.7
  Top Layer w6: S1.5@1469.21,85.15 1469.21,98.55 1490.23,119.57 1550.95,119.57 1588.43,82.09 1633.92,82.09 1677.62,125.79 1718.66,125.79 1732.26,139.39 v2(1770.82,139.39) ; v2(1809.25,609.98) U15.5@1837.33,609.98 ; v2(1898.56,687.89) 1898.56,671.88 R100.1@1902.29,668.16 U15.1@1902.29,636.55
  L6_SIGNAL 4 w6: v2(1770.82,139.39) 1708.62,201.6 1687.77,201.6 1639.9,249.46 1639.9,425.93 1664.17,450.2 1725.85,450.2 1737.85,438.21 1763.97,438.21 1783.04,457.28 1783.04,495.46 1795.04,507.45 1795.04,526.22 1826.72,557.9 1826.72,592.51 v2(1809.25,609.98)
  Bottom Layer w6: v2(1809.25,609.98) 1822.71,609.98 1900.62,687.89 v2(1898.56,687.89)
NetC34_2: C34.2 C35.2 R43.1 U2.8 | length 176.8
  Top Layer w16: R43.1@553.88,878.41 U2.8@553.88,926.95 554.16,926.67 C34.2@616.01,926.67 C35.2@616.01,860.63
NetC37_2: C37.2 R69.1 U5.3 | length 120.2
  Top Layer w6: v2(407.64,492.41) U5.3@452.64,492.41
  Bottom Layer w6: R69.1@371.69,531.67 C37.2@371.69,492.41 v2(407.64,492.41)
NetC39_2: C39.2 R68.1 R79.2 | length 100
  Bottom Layer w15: R68.1@199.63,400.74 C39.2@199.63,450.74 R79.2@199.63,500.74
NetC40_2: C40.2 R82.1 U12.3 | length 119.3
  Top Layer w15: v2(328.93,275.13) U12.3@375.78,275.13
  Bottom Layer w15: R82.1@256.48,275.13 C40.2@293.22,275.13 v2(328.93,275.13)
NetC42_2: C42.2 R81.1 R86.2 | length 100
  Bottom Layer w6: R81.1@186.67,81.4 C42.2@186.67,131.4 R86.2@186.67,181.4
NetC71_1: C71.1 U9.4 | length 59.5
  Top Layer w15: U9.4@876.14,1243.9 880.63,1248.39 C71.1@933.74,1248.39
NetD1_2: D1.2 L9.2 | length 49.1
  Top Layer w20: D1.2@1937.91,61.77 L9.2@1937.91,110.83
NetD2_2: D2.2 L10.2
NetD3_1: D3.1 R172.1 | length 51.2
  Top Layer w6: R172.1@679.5,406.64 D3.1@679.5,457.8
NetD3_2: D3.2 Q2.3 | length 162.3
  Top Layer w6: Q2.3@611.42,326 602.58,326 586.37,342.22 586.37,417.46 622.42,453.52 D3.2@622.42,457.8
NetD4_1: D4.1 U14.17 | length 61.4
  Top Layer w6: D4.1@1604.25,263.23 1620.08,263.23 1639.8,243.51 U14.17@1657.48,243.51
NetD4_2: D4.2 R99.2 | length 44.2
  Top Layer w6: R99.2@1604.25,183.64 D4.2@1604.25,227.79
NetD5_1: D5.1 R141.2 | length 43
  Top Layer w6: R141.2@302.97,1403.17 D5.1@345.96,1403.17
NetD5_2: D5.2 Q1.3 | length 54.5
  Top Layer w6: D5.2@345.96,1438.6 Q1.3@400.43,1438.6
NetD6_1: D6.1 R174.2 | length 48.7
  Top Layer w10: D6.1@1292.34,480.04 R174.2@1292.34,528.75
NetD7_2: D7.2 R212.1 | length 44
  Top Layer w12: R212.1@1893.02,1576.82 D7.2@1893.02,1620.81
NetJ1_8: J1.8 R17.2 | length 222.8
  Top Layer w6: R17.2@1902.85,876.15 1968.09,876.15 v2(1972.11,880.17)
  Bottom Layer w6: J1.8@1821.54,883.39 1912.94,883.39 1916.16,880.17 v2(1972.11,880.17)
NetJ1_10: J1.10 R15.2 | length 164.4
  Top Layer w6: R15.2@1902.85,914.52 1927.07,914.52 v2(1941,900.59)
  Bottom Layer w6: J1.10@1821.54,903.08 1913.93,903.08 1916.42,900.59 v2(1941,900.59)
NetJ1_11: J1.11 R5.2 | length 214.2
  Bottom Layer w6: R5.2@1438.42,810.89 1457.25,829.72 1457.25,847.39 1532.62,922.76 J1.11@1595.95,922.76
NetJ1_12: J1.12 R42.2 | length 101.4
  Bottom Layer w6: J1.12@1821.54,922.76 1822.07,922.23 1911.35,922.23 R42.2@1919.39,930.27
NetJ1_13: J1.13 R8.1 | length 197.7
  Bottom Layer w6: R8.1@1438.42,845.53 1527.65,934.76 1545.04,934.76 1552.73,942.45 J1.13@1595.95,942.45
NetJ1_14: J1.14 R13.1 | length 119.5
  Bottom Layer w6: J1.14@1821.54,942.45 1864.76,942.45 1872.98,934.23 1893.3,934.23 1906.36,947.29 1906.36,954.81 R13.1@1919.37,967.82
NetJ1_15: J1.15 R6.1 | length 191.5
  Bottom Layer w6: R6.1@1438.42,880.18 1468.54,910.29 1474.5,910.29 1510.97,946.76 1537.36,946.76 1552.73,962.13 J1.15@1595.95,962.13
NetJ1_16: J1.16 R10.1 | length 97.3
  Top Layer w6: R10.1@1857.66,950.58 1862.44,955.36 v2(1885.85,955.36)
  Bottom Layer w6: J1.16@1821.54,962.13 1879.08,962.13 v2(1885.85,955.36)
NetJ1_17: J1.17 R4.1 | length 181.9
  Bottom Layer w6: R4.1@1437.96,923.97 1471.21,923.97 1506,958.76 1529.67,958.76 1552.73,981.82 J1.17@1595.95,981.82
NetJ1_18: J1.18 R31.1 | length 107.6
  Bottom Layer w6: J1.18@1821.54,981.82 1895.68,981.82 R31.1@1919.37,1005.51
NetJ1_19: J1.19 R7.2 | length 164.4
  Top Layer w6: R7.2@1627.75,935.2 1647.63,955.08 v2(1677.37,955.08)
  Bottom Layer w6: J1.19@1595.95,1001.5 1639.01,1001.5 1657.79,982.73 1657.79,972.65 1675.35,955.08 v2(1677.37,955.08)
NetJ1_21: J1.21 R9.2 | length 172.4
  Bottom Layer w6: R9.2@1456.73,958.34 1456.73,970.62 1488.64,1002.53 1511.91,1002.53 1530.57,1021.19 J1.21@1595.95,1021.19
NetJ1_22: J1.22 R36.1 | length 548.2
  Top Layer w6: R36.1@1858.34,988.39 1886.85,988.39 1955.48,1057.02 1955.48,1151.22 v2(1979.15,1174.89)
  Bottom Layer w6: J1.22@1821.54,1021.19 1822.46,1022.11 1942,1022.11 1986.3,1066.41 1986.3,1150.7 1979.15,1157.86 v2(1979.15,1174.89)
NetJ1_23: J1.23 R11.2 | length 167.5
  Top Layer w6: R11.2@1627.75,975.28 1640.62,988.15 v2(1677.98,988.15)
  Bottom Layer w6: J1.23@1595.95,1040.87 1639.05,1040.87 1657.77,1022.15 1657.77,1008.36 v2(1677.98,988.15)
NetJ1_24: J1.24 R16.1 | length 188.9
  Bottom Layer w6: J1.24@1821.54,1040.87 1908.2,1040.87 1914.97,1034.11 1931.7,1034.11 1964.4,1066.8 R16.1@1964.4,1096.49
NetJ1_25: J1.25 R12.1 | length 158.9
  Top Layer w6: R12.1@1627.75,1015.36 1631.32,1018.92 v2(1677.97,1018.92)
  Bottom Layer w6: J1.25@1595.95,1060.56 1649.9,1060.56 1659.9,1050.55 1659.9,1036.99 v2(1677.97,1018.92)
NetJ1_27: J1.27 R18.2 | length 153.5
  Top Layer w6: R18.2@1627.75,1055.44 1635.87,1047.32 v2(1680.1,1047.32)
  Bottom Layer w6: J1.27@1595.95,1080.24 1647.19,1080.24 v2(1680.1,1047.32)
NetJ1_28: J1.28 R22.1 | length 162
  Top Layer w5.2: R22.1@1876.78,1052.42 1879.66,1052.42 1909.95,1082.71 v2(1922.48,1082.71)
  Bottom Layer w5.2: J1.28@1821.54,1080.24 1862.24,1080.24 1866.82,1084.82 1903.3,1084.82 1905.41,1082.71 v2(1922.48,1082.71)
NetJ1_29: J1.29 R19.2 | length 188.3
  Bottom Layer w6: R19.2@1461.73,1026.09 1466.33,1030.68 1476.31,1030.68 1493.34,1047.71 1493.34,1065.72 1502.29,1074.67 1502.29,1090.47 1516.22,1104.4 1550.46,1104.4 1554.93,1099.93 J1.29@1595.95,1099.93
NetJ1_30: J1.30 R24.1 | length 183
  Top Layer w5.2: R24.1@1876.78,1087.42 1886.08,1078.12 1890.94,1078.12 1900.68,1087.86 1900.68,1108.63 1904.6,1112.55 v2(1921.93,1112.55)
  Bottom Layer w5.2: J1.30@1821.54,1099.93 1862.23,1099.93 1867.14,1095.02 1902.28,1095.02 v2@1919.81,1112.55
NetJ1_31: J1.31 R20.2 | length 249.6
  Bottom Layer w6: R20.2@1396.27,1042.27 1399.5,1045.5 1470.82,1045.5 1477.98,1052.66 1477.98,1069.43 1490.29,1081.74 1490.29,1095.44 1514.46,1119.61 J1.31@1595.95,1119.61
NetJ1_33: J1.33 R21.2 | length 179.6
  Top Layer w6: R21.2@1627.75,1095.52 1645.81,1077.46 v2(1678.81,1077.46)
  Bottom Layer w6: J1.33@1595.95,1139.3 1638.48,1139.3 1652.51,1125.27 1652.51,1103.76 v2(1678.81,1077.46)
NetJ1_34: J1.34 R30.1 | length 105.2
  Top Layer w5.2: R30.1@1876.78,1136.89 1878.84,1138.95 v2(1901.28,1138.95)
  Bottom Layer w5.2: J1.34@1821.54,1139.3 1862.96,1139.3 1863.3,1138.95 v2(1901.28,1138.95)
NetJ1_35: J1.35 R23.2 | length 196.9
  Bottom Layer w6: R23.2@1456.73,1062.27 1456.73,1065.16 1473.93,1082.35 1473.93,1096.05 1507.95,1130.07 1507.95,1143.56 1523.38,1158.98 J1.35@1595.95,1158.98
NetJ1_36: J1.36 R32.1 | length 111.9
  Top Layer w5.2: R32.1@1876.78,1171.89 1881.32,1167.35 v2(1902.42,1167.35)
  Bottom Layer w5.2: J1.36@1821.54,1158.98 1879.04,1158.98 1887.41,1167.35 v2(1902.42,1167.35)
NetJ1_37: J1.37 R26.2 | length 180.3
  Bottom Layer w6: R26.2@1456.73,1096.91 1491.88,1132.05 1491.88,1144.45 1526.09,1178.67 J1.37@1595.95,1178.67
NetJ1_39: J1.39 R27.2 | length 161.9
  Bottom Layer w6: R27.2@1461.73,1131.56 1528.53,1198.35 J1.39@1595.95,1198.35
NetJ1_40: J1.40 R33.1 | length 195.2
  Top Layer w5.2: R33.1@1876.78,1232.24 1883.63,1239.09 1893.6,1239.09 1905.81,1226.89 1905.81,1212.01 v2(1927.34,1190.48)
  Bottom Layer w5.2: J1.40@1821.54,1198.35 1862.22,1198.35 1866.96,1203.09 1914.72,1203.09 v2(1927.34,1190.48)
NetJ1_41: J1.41 R28.2 | length 155.7
  Bottom Layer w6: R28.2@1461.73,1166.2 1505.89,1210.35 1535.09,1210.35 1542.78,1218.04 J1.41@1595.95,1218.04
NetJ1_42: J1.42 R35.1 | length 191.9
  Top Layer w5.2: R35.1@1876.78,1270.22 1876.78,1254.66 1882.15,1249.29 1897.83,1249.29 1925.98,1221.14 v2(1927.77,1221.14)
  Bottom Layer w5.2: J1.42@1821.54,1218.04 1862.89,1218.04 1867.64,1213.29 1901.14,1213.29 1908.98,1221.14 v2(1927.77,1221.14)
NetJ1_43: J1.43 R60.1 | length 149.5
  Bottom Layer w6: R60.1@1461.73,1200.84 1483.27,1222.38 1530.15,1222.38 1545.49,1237.72 J1.43@1595.95,1237.72
NetJ1_45: J1.45 R61.1 | length 143.3
  Bottom Layer w6: R61.1@1461.73,1235.48 1526.28,1235.48 1548.21,1257.41 J1.45@1595.95,1257.41
NetJ1_46: J1.46 R39.1 | length 248.6
  Top Layer w5.2: R39.1@1876.78,1334.43 1890.67,1348.32 1896.38,1348.32 1902.94,1341.76 1902.94,1305.08 1896.93,1299.07 1896.93,1281.5 v2(1925.87,1252.57)
  Bottom Layer w5.2: J1.46@1821.54,1257.41 1862.17,1257.41 1866.91,1262.15 1916.28,1262.15 v2(1925.87,1252.57)
NetJ1_47: J1.47 R62.1 | length 139.5
  Bottom Layer w6: R62.1@1461.73,1270.13 1471.58,1279.97 1536.45,1279.97 1539.33,1277.09 J1.47@1595.95,1277.09
NetJ1_48: J1.48 R41.1 | length 247.9
  Top Layer w5.2: R41.1@1876.78,1372.41 1890.67,1358.52 1900.6,1358.52 1913.14,1345.98 1913.14,1333.17 1918.98,1327.33 1918.98,1314.67 1913.14,1308.83 1913.14,1300.86 1907.13,1294.84 1907.13,1285.73 1912.28,1280.58 1922.88,1280.58 v2(1925.87,1283.57)
  Bottom Layer w5.2: J1.48@1821.54,1277.09 1862.37,1277.09 1867.11,1272.35 1914.65,1272.35 v2(1925.87,1283.57)
NetJ1_49: J1.49 R63.1 | length 141.5
  Bottom Layer w6: R63.1@1461.73,1304.77 1474.53,1291.97 1538.17,1291.97 1542.98,1296.78 J1.49@1595.95,1296.78
NetJ1_51: J1.51 R64.1 | length 142.9
  Bottom Layer w5: R64.1@1487.99,1387.77 1508.75,1367.01 1508.75,1358.04 1547.74,1319.05 1547.74,1318.77 1593.64,1318.77 J1.51@1595.95,1316.46
NetJ1_52: J1.52 R58.1 | length 96.8
  Bottom Layer w6: J1.52@1821.54,1316.46 R58.1@1918.31,1316.46
NetJ1_53: J1.53 R34.2 | length 159.5
  Bottom Layer w5: R34.2@1487.99,1421.77 1519.75,1390.01 1519.75,1362.6 1546.2,1336.15 J1.53@1595.95,1336.15
NetJ1_54: J1.54 R59.1 | length 104.5
  Bottom Layer w6: J1.54@1821.54,1336.15 1899.75,1336.15 R59.1@1918.31,1354.7
NetJ1_55: J1.55 R37.2 | length 157.2
  Bottom Layer w5: R37.2@1527.99,1455.77 1547.7,1436.06 1547.7,1411.61 1542.62,1406.53 1542.62,1366.65 1553.44,1355.83 J1.55@1595.95,1355.83
NetJ1_56: J1.56 R65.2 | length 288.2
  Bottom Layer w6: J1.56@1821.54,1355.83 1870.75,1355.83 1888.96,1374.04 1888.96,1447.53 1885,1451.49 1885,1468.05 1921.19,1504.24 1927.46,1504.24 R65.2@1970,1546.78
NetJ1_57: J1.57 R38.2 | length 308.1
  Bottom Layer w5.98: J1.57@1595.95,1375.52 1644.39,1375.52 1652.84,1383.97 1652.84,1563.42 1671.97,1582.55 1709.23,1582.55 R38.2@1712.01,1579.77
NetJ1_58: J1.58 R66.1 | length 249.7
  Bottom Layer w6: J1.58@1821.54,1375.52 1869.68,1375.52 1876.96,1382.8 1876.96,1442.56 1873,1446.52 1873,1484.78 R66.1@1935,1546.78
NetJ1_59: J1.59 R40.2 | length 307.9
  Bottom Layer w5.98: J1.59@1595.95,1395.2 1633.14,1395.2 1640.48,1402.54 1640.48,1574.75 1680.5,1614.77 R40.2@1712.01,1614.77
NetJ1_60: J1.60 R67.1 | length 208.7
  Bottom Layer w6: J1.60@1821.54,1395.2 1858.01,1395.2 1864.96,1402.15 1864.96,1428.66 1861,1432.62 1861,1490.47 1900,1529.47 R67.1@1900,1546.78
NetJ2_21: J2.21 R137.1 | length 162
  Top Layer w5.2: v2(211.97,968.04) 245.27,968.04 R137.1@247.01,969.77
  Bottom Layer w5.2: v2(211.97,968.04) 234,990.07 234,1010.05 245.14,1021.19 J2.21@304.44,1021.19
NetJ2_23: J2.23 R136.1 | length 145.2
  Top Layer w5.2: v2(211,1003.77) 246.01,1003.77 R136.1@247.01,1004.77
  Bottom Layer w5.2: v2(211,1003.77) 213.3,1003.77 240.92,1031.39 247.13,1031.39 256.61,1040.87 J2.23@304.44,1040.87
NetJ2_27: J2.27 R135.1 | length 113
  Top Layer w5.2: v2(219.68,1080.24) 244.78,1080.24 R135.1@247.01,1078.02
  Bottom Layer w5.2: v2(219.68,1080.24) J2.27@304.44,1080.24
NetJ2_29: J2.29 R134.1 | length 120.3
  Top Layer w5.2: v2(219.68,1116.4) 223.06,1113.02 R134.1@247.01,1113.02
  Bottom Layer w5.2: v2(219.68,1116.4) 236.15,1099.93 J2.29@304.44,1099.93
NetJ2_34: J2.34 R132.2 | length 121.2
  Bottom Layer w6: J2.34@530.04,1139.3 581.22,1139.3 R132.2@630.75,1089.77
NetJ2_36: J2.36 R130.2 | length 114.9
  Bottom Layer w6: J2.36@530.04,1158.98 596.54,1158.98 R130.2@630.75,1124.77
NetJ2_38: J2.38 R129.2 | length 108.5
  Bottom Layer w6: J2.38@530.04,1178.67 531.93,1176.77 597.51,1176.77 614.51,1159.77 R129.2@630.75,1159.77
NetJ2_39: J2.39 R133.1 | length 127.8
  Top Layer w5.2: v2(222.53,1164.51) 241.22,1164.51 244.45,1161.28 R133.1@247.01,1163.84
  Bottom Layer w5.2: v2(222.53,1164.51) 225.33,1164.51 240.92,1180.1 240.92,1188.58 250.7,1198.35 J2.39@304.44,1198.35
NetJ2_40: J2.40 R128.2 | length 104.3
  Bottom Layer w6: J2.40@530.04,1198.35 573.26,1198.35 581.84,1189.77 R128.2@630.75,1189.77
NetJ2_41: J2.41 R131.1 | length 115.2
  Top Layer w5.2: v2(222.1,1202.22) 243.63,1202.22 R131.1@247.01,1198.84
  Bottom Layer w5.2: v2(222.1,1202.22) 237.92,1218.04 J2.41@304.44,1218.04
NetJ2_42: J2.42 R127.2 | length 112.8
  Bottom Layer w6: J2.42@530.04,1218.04 573.26,1218.04 584.45,1206.85 612.26,1206.85 630.18,1224.77 R127.2@630.75,1224.77
NetJ2_44: J2.44 R126.2 | length 109.8
  Bottom Layer w6: J2.44@530.04,1237.72 573.26,1237.72 595.3,1259.77 R126.2@630.75,1259.77
NetJ2_46: J2.46 R125.2 | length 131.2
  Bottom Layer w6: J2.46@530.04,1257.41 573.25,1257.41 587.62,1271.77 605.44,1271.77 628.44,1294.77 R125.2@645.75,1294.77
NetJ2_48: J2.48 R124.2 | length 137.5
  Bottom Layer w6: J2.48@530.04,1277.09 573.25,1277.09 580.94,1284.78 597.68,1284.78 642.68,1329.77 R124.2@645.75,1329.77
NetJ2_50: J2.50 R140.2 | length 151.3
  Bottom Layer w6: J2.50@530.04,1296.78 590.5,1296.78 627.7,1333.97 627.7,1346.72 R140.2@645.75,1364.77
NetJ3_1: J3.1 R79.1 U5.6 | length 235.4
  Top Layer w6: J3.1@87.13,498.74 93.46,492.41 U5.6@245.94,492.41
  Bottom Layer w6: J3.1@87.13,498.74 89.13,500.74 R79.1@160.26,500.74
NetJ3_3: J3.3 R68.2 U5.7 | length 250.9
  Top Layer w6: J3.3@87.13,398.74 130.8,442.41 U5.7@245.94,442.41
  Bottom Layer w6: J3.3@87.13,398.74 158.26,398.74 R68.2@160.26,400.74
NetJ4_1: J4.1 R86.1 U12.6 | length 196
  Top Layer w6: J4.1@87.13,181.4 96.05,190.31 96.05,215.93 155.24,275.13 U12.6@169.09,275.13
  Bottom Layer w6: J4.1@87.13,181.4 R86.1@147.3,181.4
NetJ4_3: J4.3 R81.2 U12.7 | length 246.6
  Top Layer w6: J4.3@87.13,81.4 130.6,124.87 130.6,201.52 154.21,225.13 U12.7@169.09,225.13
  Bottom Layer w6: J4.3@87.13,81.4 R81.2@147.3,81.4
NetJ6_1: J6.1 J6.2 J6.3 R122.2 | length 64.2
  Bottom Layer w10.98: J6.2@934.31,117.69 934.31,181.89
NetJ6_20: J6.20 R217.1 | length 1960.2
  Top Layer w5.2: R217.1@339.59,1198.84 351.99,1186.44 356.65,1186.44 361.67,1191.45 361.67,1194.89 381.62,1214.84 v2(382.93,1214.84)
  L3_SIGNAL 1 w4.8: v2(382.93,1214.84) 374.44,1206.35 308.15,1206.35 288.19,1186.38 288.19,863.12 259.76,834.7 259.76,679.52 306.91,632.37 306.91,574.51 349.55,531.87 452.8,531.87 562.27,422.4 562.27,400.71 659.64,303.35 689.63,303.35 796.55,196.43 839.69,196.43 961.7,74.42 1110.17,74.42 1115.31,69.27 1115.31,53.17 v2(1101.57,39.43)
  Bottom Layer w5.2: v2(1101.57,39.43) 1111.47,49.32 J6.20@1111.47,117.69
